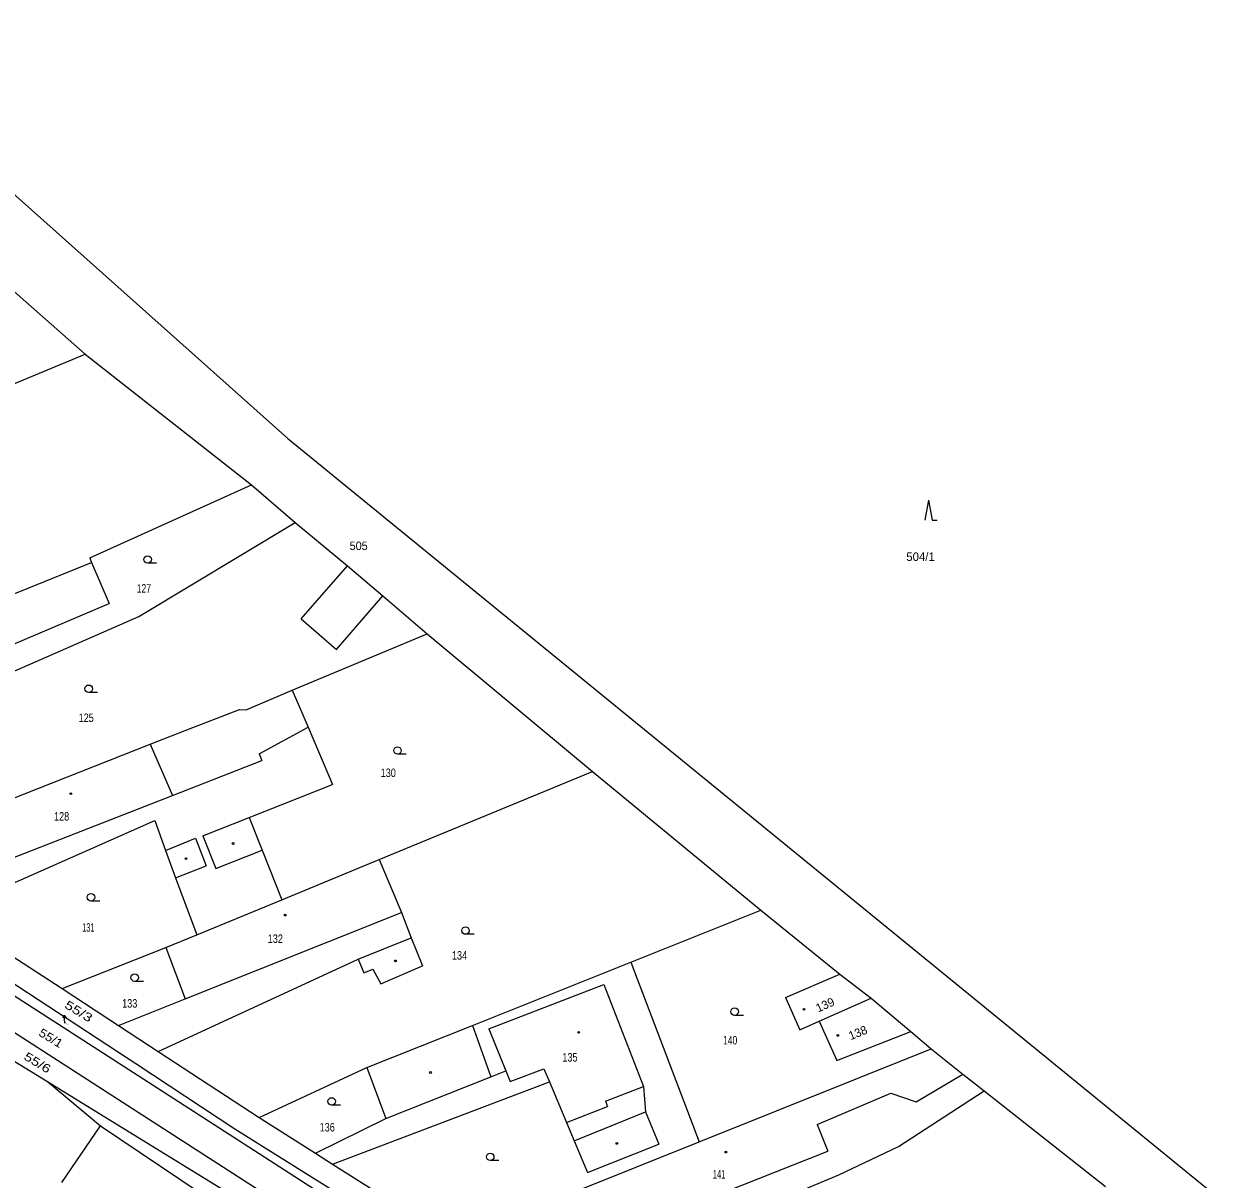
# Model space of a CAD drawing. Extents: x -592965 to -592390, y -1145071 to -1144631.
# Drawn here: x -592620.1 to -592501.4, y -1144793.9 to -1144678.4 of the extents above; entities that cross this region are included whole.
import ezdxf

# ---------------------------------------------------------------- set-up
doc = ezdxf.new("R2010")
doc.units = 0
doc.header["$LTSCALE"] = 0.17
doc.layers.add('4', color=7, linetype='Continuous', lineweight=25)

msp = doc.modelspace()

# ---------------------------------------------------------------- linework, layer by layer
at = {"layer": '4'}
for p, q in [((-592640.18, -1144678.35), (-592593.65, -1144719.8)), ((-592629.42, -1144697.69), (-592613.93, -1144711.39)), ((-592638.1, -1144721.33), (-592613.93, -1144711.39)), ((-592613.93, -1144711.39), (-592597.3, -1144724.45)), ((-592593.65, -1144719.8), (-592501.36, -1144795.12)), ((-592613.46, -1144731.74), (-592597.3, -1144724.45)), ((-592597.3, -1144724.45), (-592592.92, -1144728.21)), ((-592529.631, -1144725.984), (-592529.998, -1144727.984)), ((-592529.631, -1144725.984), (-592529.264, -1144727.984)), ((-592529.264, -1144727.984), (-592528.764, -1144727.984)), ((-592608.55, -1144737.6), (-592592.92, -1144728.21)), ((-592592.92, -1144728.21), (-592587.71, -1144732.52)), ((-592635.82, -1144741.28), (-592613.27, -1144732.2)), ((-592613.46, -1144731.74), (-592613.27, -1144732.2)), ((-592613.27, -1144732.2), (-592611.53, -1144736.31)), ((-592606.795, -1144732.28), (-592607.67, -1144732.28)), ((-592587.71, -1144732.52), (-592584.18, -1144735.55)), ((-592624.58, -1144741.83), (-592611.53, -1144736.31)), ((-592584.18, -1144735.55), (-592579.72, -1144739.34)), ((-592593.23, -1144744.95), (-592579.72, -1144739.34)), ((-592579.72, -1144739.34), (-592563.2, -1144753.11)), ((-592612.685, -1144745.2), (-592613.56, -1144745.2)), ((-592597.84, -1144746.92), (-592593.23, -1144744.95)), ((-592593.23, -1144744.95), (-592591.64, -1144748.68)), ((-592603.17, -1144748.71), (-592598.49, -1144746.9)), ((-592598.49, -1144746.9), (-592597.84, -1144746.92)), ((-592607.41, -1144750.36), (-592603.17, -1144748.71)), ((-592591.64, -1144748.68), (-592589.2, -1144754.39)), ((-592626.64, -1144757.96), (-592607.41, -1144750.36)), ((-592581.825, -1144751.37), (-592582.7, -1144751.37)), ((-592584.53, -1144761.9), (-592563.2, -1144753.11)), ((-592563.2, -1144753.11), (-592546.38, -1144766.95)), ((-592597.52, -1144757.68), (-592589.2, -1144754.39)), ((-592597.52, -1144757.68), (-592596.22, -1144760.96)), ((-592623.53, -1144765.34), (-592606.96, -1144757.99)), ((-592606.96, -1144757.99), (-592605.88, -1144761)), ((-592605.88, -1144761), (-592604.88, -1144763.71)), ((-592584.53, -1144761.9), (-592582.3, -1144767.18)), ((-592604.88, -1144763.71), (-592602.76, -1144769.41)), ((-592612.465, -1144766.04), (-592613.34, -1144766.04)), ((-592602.76, -1144769.41), (-592594.26, -1144765.91)), ((-592559.38, -1144772.15), (-592546.38, -1144766.95)), ((-592546.38, -1144766.95), (-592538.47, -1144773.35)), ((-592626.39, -1144768.19), (-592616.23, -1144774.8)), ((-592605.86, -1144770.69), (-592602.76, -1144769.41)), ((-592575.025, -1144769.37), (-592575.9, -1144769.37)), ((-592616.23, -1144774.8), (-592605.86, -1144770.69)), ((-592605.86, -1144770.69), (-592603.91, -1144775.81)), ((-592627.84, -1144771.11), (-592589.96, -1144795.52)), ((-592624.9, -1144771.77), (-592618.62, -1144775.89)), ((-592606.62, -1144781.09), (-592586.64, -1144771.87)), ((-592586.64, -1144771.87), (-592586.08, -1144773.23)), ((-592586.08, -1144773.23), (-592585.17, -1144772.86)), ((-592585.17, -1144772.86), (-592584.37, -1144774.31)), ((-592584.37, -1144774.31), (-592580.19, -1144772.53)), ((-592575.2, -1144778.47), (-592559.38, -1144772.15)), ((-592559.38, -1144772.15), (-592552.56, -1144790.13)), ((-592630.17, -1144773.28), (-592589.61, -1144799.37)), ((-592608.095, -1144774.07), (-592608.97, -1144774.07)), ((-592573.57, -1144778.81), (-592562.06, -1144774.38)), ((-592562.06, -1144774.38), (-592558.11, -1144784.58)), ((-592543.91, -1144775.69), (-592538.47, -1144773.35)), ((-592538.47, -1144773.35), (-592535.35, -1144775.75)), ((-592616.23, -1144774.8), (-592610.6, -1144778.48)), ((-592618.62, -1144775.89), (-592608.86, -1144782.28)), ((-592610.6, -1144778.48), (-592603.91, -1144775.81)), ((-592543.91, -1144775.69), (-592542.49, -1144778.92)), ((-592540.54, -1144778.06), (-592535.35, -1144775.75)), ((-592535.35, -1144775.75), (-592531.4, -1144779.07)), ((-592548.125, -1144777.47), (-592549, -1144777.47)), ((-592610.6, -1144778.48), (-592606.62, -1144781.09)), ((-592585.76, -1144782.69), (-592575.2, -1144778.47)), ((-592575.2, -1144778.47), (-592573.37, -1144783.6)), ((-592573.57, -1144778.81), (-592571.88, -1144783.01)), ((-592542.49, -1144778.92), (-592540.54, -1144778.06)), ((-592540.54, -1144778.06), (-592538.79, -1144781.99)), ((-592538.79, -1144781.99), (-592531.4, -1144779.07)), ((-592606.62, -1144781.09), (-592596.54, -1144787.67)), ((-592552.56, -1144790.13), (-592529.36, -1144780.83)), ((-592608.86, -1144782.28), (-592598.96, -1144788.81)), ((-592596.54, -1144787.67), (-592585.76, -1144782.69)), ((-592585.76, -1144782.69), (-592583.86, -1144787.78)), ((-592573.37, -1144783.6), (-592571.88, -1144783.01)), ((-592526.19, -1144783.36), (-592524.07, -1144785.03)), ((-592617.69, -1144784.09), (-592613.84, -1144786.45)), ((-592617.69, -1144784.09), (-592612.39, -1144788.53)), ((-592589.18, -1144792.33), (-592567.52, -1144784.1)), ((-592567.52, -1144784.1), (-592565.81, -1144788.18)), ((-592532.61, -1144790.59), (-592524.07, -1144785.03)), ((-592524.07, -1144785.03), (-592511.92, -1144794.58)), ((-592613.84, -1144786.45), (-592586.25, -1144803.41)), ((-592588.405, -1144786.45), (-592589.28, -1144786.45)), ((-592612.39, -1144788.53), (-592596.93, -1144798.89)), ((-592596.54, -1144787.67), (-592590.9, -1144791.24)), ((-592590.9, -1144791.24), (-592583.86, -1144787.78)), ((-592565.81, -1144788.18), (-592565.04, -1144790.02)), ((-592598.96, -1144788.81), (-592586.05, -1144796.87)), ((-592565.34, -1144795.24), (-592552.56, -1144790.13)), ((-592565.04, -1144790.02), (-592563.72, -1144793.18)), ((-592563.72, -1144793.18), (-592556.58, -1144790.35)), ((-592538.58, -1144793.41), (-592532.61, -1144790.59)), ((-592590.9, -1144791.24), (-592589.18, -1144792.33)), ((-592572.555, -1144791.99), (-592573.43, -1144791.99)), ((-592589.18, -1144792.33), (-592575.67, -1144800.88)), ((-592567.15, -1144805.34), (-592538.58, -1144793.41))]:
    msp.add_line(p, q, dxfattribs=at)
at = {"layer": '4', "lineweight": 13}
for p, q in [((-592592.32, -1144737.84), (-592587.71, -1144732.52)), ((-592588.81, -1144740.89), (-592584.18, -1144735.55)), ((-592592.32, -1144737.84), (-592588.81, -1144740.89)), ((-592596.51, -1144751.33), (-592591.64, -1144748.68)), ((-592607.41, -1144750.36), (-592605.19, -1144755.48)), ((-592596.51, -1144751.33), (-592596.26, -1144751.99)), ((-592605.19, -1144755.48), (-592596.26, -1144751.99)), ((-592624.63, -1144763.09), (-592605.19, -1144755.48)), ((-592602.16, -1144759.52), (-592597.52, -1144757.68)), ((-592605.88, -1144761), (-592602.88, -1144759.76)), ((-592602.88, -1144759.76), (-592601.81, -1144762.51)), ((-592602.16, -1144759.52), (-592600.86, -1144762.8)), ((-592600.86, -1144762.8), (-592596.22, -1144760.96)), ((-592604.88, -1144763.71), (-592601.81, -1144762.51)), ((-592603.91, -1144775.81), (-592582.3, -1144767.18)), ((-592586.64, -1144771.87), (-592581.34, -1144769.71)), ((-592615.95, -1144778.24), (-592616.006, -1144777.446)), ((-592583.86, -1144787.78), (-592573.37, -1144783.6)), ((-592530.86, -1144786.1), (-592526.19, -1144783.36)), ((-592561.9, -1144786.05), (-592558.11, -1144784.58)), ((-592561.9, -1144786.05), (-592561.7, -1144786.59)), ((-592540.74, -1144788.37), (-592533.38, -1144785.25)), ((-592533.38, -1144785.25), (-592530.86, -1144786.1)), ((-592565.81, -1144788.18), (-592561.7, -1144786.59)), ((-592565.04, -1144790.02), (-592557.9, -1144787.1)), ((-592616.26, -1144794.19), (-592612.39, -1144788.53)), ((-592540.74, -1144788.37), (-592539.69, -1144791.03)), ((-592563.45, -1144800.45), (-592539.69, -1144791.03))]:
    msp.add_line(p, q, dxfattribs=at)
at = {"layer": '4'}
for points in [[(-592624.58, -1144741.83), (-592624.28, -1144742.7), (-592623.72, -1144744.23), (-592608.55, -1144737.6)], [(-592596.22, -1144760.96), (-592594.26, -1144765.91), (-592584.53, -1144761.9)], [(-592642.94, -1144765.13), (-592635.39, -1144771.11), (-592623.31, -1144780.66), (-592623.2, -1144780.73), (-592617.69, -1144784.09)], [(-592582.3, -1144767.18), (-592581.34, -1144769.71), (-592580.19, -1144772.53)], [(-592531.4, -1144779.07), (-592529.36, -1144780.83), (-592526.19, -1144783.36)], [(-592558.11, -1144784.58), (-592557.9, -1144787.1), (-592556.58, -1144790.35)]]:
    msp.add_lwpolyline(points, dxfattribs=at)
at = {"layer": '4', "lineweight": 13}
for points in [[(-592616.12, -1144777.72), (-592616.006, -1144777.446), (-592615.855, -1144777.701)], [(-592571.88, -1144783.01), (-592571.45, -1144784.09), (-592568.06, -1144782.82), (-592567.52, -1144784.1)]]:
    msp.add_lwpolyline(points, dxfattribs=at)
at = {"layer": '4'}
for centre, radius in [((-592607.67, -1144731.905), 0.375), ((-592613.56, -1144744.825), 0.375), ((-592582.7, -1144750.995), 0.375), ((-592615.36, -1144755.31), 0.0875), ((-592599.13, -1144760.29), 0.0875), ((-592603.84, -1144761.8), 0.0875), ((-592613.34, -1144765.665), 0.375), ((-592593.92, -1144767.45), 0.0875), ((-592575.9, -1144768.995), 0.375), ((-592582.9, -1144772.03), 0.0875), ((-592608.97, -1144773.695), 0.375), ((-592549, -1144777.095), 0.375), ((-592542.07, -1144776.86), 0.0875), ((-592564.59, -1144779.18), 0.0875), ((-592538.69, -1144779.48), 0.0875), ((-592579.4, -1144783.18), 0.0875), ((-592589.28, -1144786.075), 0.375), ((-592560.77, -1144790.27), 0.0875), ((-592549.87, -1144791.14), 0.0875), ((-592573.43, -1144791.615), 0.375)]:
    msp.add_circle(centre, radius, dxfattribs=at)

# ---------------------------------------------------------------- texts
for s, width, p in [('505', 0.95, (-592587.48, -1144730.96)), ('127', 0.75, (-592608.76, -1144735.22)), ('125', 0.8, (-592614.57, -1144748.15)), ('130', 0.8, (-592584.38, -1144753.65)), ('128', 0.8, (-592617.03, -1144758)), ('131', 0.6, (-592614.22, -1144769.11)), ('132', 0.8, (-592595.67, -1144770.23)), ('134', 0.8, (-592577.26, -1144771.9)), ('133', 0.8, (-592610.22, -1144776.7)), ('140', 0.75, (-592550.16, -1144780.38)), ('135', 0.8, (-592566.22, -1144782.09)), ('136', 0.8, (-592590.48, -1144789.08)), ('141', 0.6, (-592551.17, -1144793.78))]:
    msp.add_text(s, height=0.85, dxfattribs=dict(at, width=width)).set_placement(p)
msp.add_text('504/1', height=0.85, dxfattribs=at).set_placement((-592531.84, -1144732.05))
for s, height, width, p in [('55/3', 0.85, 1.35, (-592616.063, -1144776.651)), ('55/1', 0.85, 1.15, (-592618.649, -1144779.441)), ('55/3', 0.1, 1.5, (-592615.95, -1144778.24)), ('55/6', 0.85, 1.3, (-592620.13, -1144781.811))]:
    msp.add_text(s, height=height, rotation=328.625, dxfattribs=dict(at, width=width)).set_placement(p)
for s, rotation, p in [('139', 23.607, (-592540.66, -1144777.19)), ('138', 22.176, (-592537.4, -1144779.96))]:
    msp.add_text(s, height=0.85, rotation=rotation, dxfattribs=at).set_placement(p)

doc.saveas('drawing.dxf')
